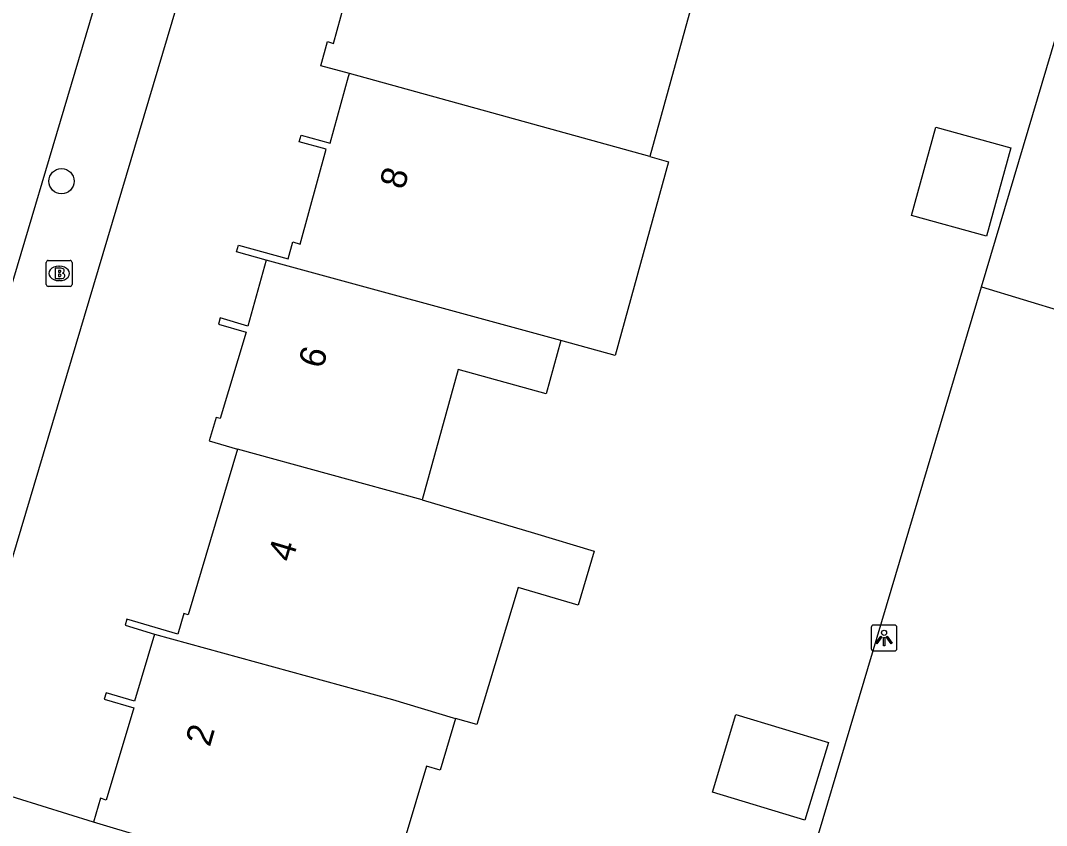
# Model space of a CAD drawing. Extents: x 162186 to 163152, y 385513 to 386513.
# Drawn here: x 162732.25 to 162771.96, y 386082.74 to 386113.9 of the extents above; entities that cross this region are included whole.
import ezdxf

# ---------------------------------------------------------------- set-up
doc = ezdxf.new("R2010")
doc.units = 0
for name, color, linetype in [('IMGEO_Boom', 7, 'Continuous'), ('IMGEO_Brandkraan', 7, 'Continuous'), ('IMGEO_Lichtpunt', 7, 'Continuous'), ('IMGEO_Pand', 7, 'Continuous'), ('IMGEO_Pand_nummerreeks', 7, 'Continuous'), ('IMGEO_Rijbaan_lokaal_open', 7, 'Continuous'), ('IMGEO_Voetpad_open', 7, 'Continuous')]:
    doc.layers.add(name, color=color, linetype=linetype)

msp = doc.modelspace()

# ---------------------------------------------------------------- linework, layer by layer
at = {"layer": 'IMGEO_Boom'}
msp.add_circle((162733.841, 386107.675), 0.489, dxfattribs=at)
at = {"layer": 'IMGEO_Brandkraan'}
for p, q in [((162733.249, 386103.681), (162733.249, 386104.533)), ((162733.324, 386104.607), (162734.176, 386104.607)), ((162733.737, 386104.387), (162733.762, 386104.387)), ((162734.25, 386104.533), (162734.25, 386103.681)), ((162734.176, 386103.607), (162733.324, 386103.607)), ((162733.76, 386103.827), (162733.735, 386103.827))]:
    msp.add_line(p, q, dxfattribs=at)
for points in [[(162733.249, 386103.681), (162733.249, 386104.533)], [(162733.324, 386104.607), (162734.176, 386104.607)], [(162733.597, 386104.307), (162733.597, 386103.907), (162733.81, 386103.907)], [(162733.828, 386104.307), (162733.597, 386104.307)], [(162734.25, 386104.533), (162734.25, 386103.681)], [(162733.776, 386104.226), (162733.722, 386104.226), (162733.722, 386104.15)], [(162733.722, 386104.15), (162733.775, 386104.15)], [(162733.784, 386104.074), (162733.722, 386104.074), (162733.722, 386103.993)], [(162733.722, 386103.993), (162733.784, 386103.993)], [(162734.176, 386103.607), (162733.324, 386103.607)]]:
    msp.add_lwpolyline(points, dxfattribs=at)
for centre, radius, start, end in [((162733.326, 386104.531), 0.0765, 91.552, 178.448), ((162733.326, 386104.531), 0.0765, 91.552, 178.448), ((162733.832, 386104.162), 0.145, 59.4692, 91.5367), ((162733.857, 386104.209), 0.0922, 285.5137, 58.1501), ((162734.174, 386104.531), 0.0765, 1.552, 88.448), ((162734.174, 386104.531), 0.0765, 1.552, 88.448), ((162733.777, 386104.188), 0.0379, 267.8285, 90.9355), ((162733.785, 386104.033), 0.0404, 269.8759, 90.5077), ((162733.816, 386104.158), 0.251, 268.6676, 293.5347), ((162733.862, 386104.017), 0.105, 301.3115, 78.989), ((162733.326, 386103.683), 0.0765, 181.552, 268.448), ((162733.326, 386103.683), 0.0765, 181.552, 268.448), ((162734.174, 386103.683), 0.0765, 271.552, 358.448), ((162734.174, 386103.683), 0.0765, 271.552, 358.448)]:
    msp.add_arc(centre, radius, start, end, dxfattribs=at)
for centre, major_axis, ratio, start_param, end_param in [((162733.736, 386104.107), (-0.387, 0.002), 0.722429, 4.712389, 7.853982), ((162733.761, 386104.107), (-0.39, 0.002), 0.717154, 1.570796, 4.712389)]:
    msp.add_ellipse(centre, major_axis=major_axis, ratio=ratio, start_param=start_param, end_param=end_param, dxfattribs=at)
at = {"layer": 'IMGEO_Lichtpunt'}
for p, q in [((162765.173, 386090.4), (162765.173, 386089.593)), ((162765.173, 386090.4), (162765.173, 386089.593)), ((162766.075, 386090.495), (162765.267, 386090.495)), ((162766.075, 386090.495), (162765.267, 386090.495)), ((162766.169, 386089.593), (162766.169, 386090.4)), ((162766.169, 386089.593), (162766.169, 386090.4)), ((162765.267, 386089.499), (162766.075, 386089.499)), ((162765.267, 386089.499), (162766.075, 386089.499))]:
    msp.add_line(p, q, dxfattribs=at)
for points in [[(162765.547, 386090.064), (162765.586, 386090.036), (162765.398, 386089.774), (162765.36, 386089.801), (162765.547, 386090.064)], [(162765.649, 386090.016), (162765.696, 386090.016), (162765.696, 386089.694), (162765.649, 386089.694), (162765.649, 386090.016)], [(162765.759, 386090.036), (162765.797, 386090.063), (162765.984, 386089.801), (162765.945, 386089.773), (162765.759, 386090.036)]]:
    msp.add_lwpolyline(points, dxfattribs=at)
msp.add_circle((162765.672, 386090.198), 0.0994, dxfattribs=at)
for centre, start, end in [((162765.267, 386090.4), 90, 180), ((162765.267, 386090.4), 90, 180), ((162766.075, 386090.4), 0, 90), ((162766.075, 386090.4), 0, 90), ((162765.267, 386089.593), 180, 270), ((162765.267, 386089.593), 180, 270), ((162766.075, 386089.593), 270, 0), ((162766.075, 386089.593), 270, 360)]:
    msp.add_arc(centre, 0.0946, start, end, dxfattribs=at)
at = {"layer": 'IMGEO_Pand'}
for points in [[(162744.982, 386111.839), (162743.872, 386112.145), (162744.129, 386113.077), (162744.368, 386113.011), (162745.366, 386116.628), (162744.272, 386116.931), (162744.34, 386117.177), (162745.53, 386116.849), (162746.257, 386119.483)], [(162755.389, 386117.025), (162757.653, 386116.399), (162758.675, 386116.117), (162756.608, 386108.631)], [(162741.758, 386104.626), (162740.618, 386104.942), (162740.689, 386105.202), (162742.609, 386104.672), (162742.789, 386105.325), (162743.077, 386105.245), (162744.089, 386108.913), (162743.037, 386109.204), (162743.109, 386109.464), (162744.24, 386109.152), (162744.951, 386111.727), (162744.982, 386111.839)], [(162756.608, 386108.631), (162744.982, 386111.839)], [(162767.679, 386109.77), (162770.582, 386108.969), (162769.637, 386105.548), (162766.734, 386106.349), (162767.679, 386109.77)], [(162756.608, 386108.631), (162757.333, 386108.43), (162755.263, 386100.934), (162753.169, 386101.512)], [(162741.758, 386104.626), (162741.053, 386102.071), (162739.987, 386102.389), (162739.914, 386102.144), (162740.981, 386101.827), (162739.986, 386098.488), (162739.824, 386098.536), (162739.553, 386097.627), (162740.655, 386097.299)], [(162753.169, 386101.512), (162741.758, 386104.626)], [(162753.169, 386101.512), (162752.598, 386099.443), (162749.191, 386100.383), (162747.794, 386095.346)], [(162740.655, 386097.299), (162738.746, 386090.892), (162738.575, 386090.943), (162738.336, 386090.144), (162736.371, 386090.729), (162736.3, 386090.49), (162737.443, 386090.149)], [(162747.794, 386095.346), (162740.655, 386097.299)], [(162747.794, 386095.346), (162752.141, 386094.051), (162754.46, 386093.36), (162753.838, 386091.271), (162751.517, 386091.957), (162749.91, 386086.652), (162749.086, 386086.882)], [(162737.443, 386090.149), (162736.667, 386087.546), (162735.563, 386087.875), (162735.49, 386087.63), (162736.634, 386087.29), (162735.572, 386083.726), (162735.351, 386083.791), (162735.074, 386082.862)], [(162737.443, 386090.149), (162746.654, 386087.61), (162748.993, 386086.91), (162749.086, 386086.882)], [(162749.086, 386086.882), (162748.488, 386084.875), (162747.961, 386085.032), (162746.315, 386079.512)], [(162763.522, 386085.955), (162762.609, 386082.944), (162759.03, 386084.029), (162759.942, 386087.04), (162763.522, 386085.955)], [(162746.315, 386079.512), (162743.573, 386080.329), (162735.074, 386082.862)]]:
    msp.add_lwpolyline(points, dxfattribs=at)
at = {"layer": 'IMGEO_Rijbaan_lokaal_open'}
for points in [[(162735.486, 386115.734), (162730.41, 386098.664), (162727.044, 386087.256)], [(162746.315, 386079.512), (162758.579, 386075.961), (162758.794, 386075.903), (162759.013, 386075.865), (162759.235, 386075.846), (162759.457, 386075.847), (162759.679, 386075.868), (162759.898, 386075.909), (162760.112, 386075.969), (162760.32, 386076.049), (162760.52, 386076.146), (162760.711, 386076.261), (162760.89, 386076.392), (162761.057, 386076.539), (162761.211, 386076.7), (162761.349, 386076.875), (162761.471, 386077.061), (162761.576, 386077.257), (162761.663, 386077.462), (162761.733, 386077.677), (162769.446, 386103.583)], [(162769.446, 386103.583), (162772.668, 386102.613)], [(162735.074, 386082.862), (162731.096, 386084.112), (162730.945, 386084.185), (162730.791, 386084.277), (162730.647, 386084.381), (162730.512, 386084.498), (162730.389, 386084.627), (162730.277, 386084.766), (162730.178, 386084.915), (162730.093, 386085.072), (162730.023, 386085.236), (162729.967, 386085.406), (162729.927, 386085.579), (162729.902, 386085.756), (162729.893, 386085.934), (162729.9, 386086.113), (162729.923, 386086.29), (162729.962, 386086.464)]]:
    msp.add_lwpolyline(points, dxfattribs=at)
at = {"layer": 'IMGEO_Voetpad_open'}
for points in [[(162729.962, 386086.464), (162748.726, 386149.462), (162748.746, 386149.525)], [(162769.446, 386103.583), (162780.141, 386139.505), (162780.193, 386139.71)]]:
    msp.add_lwpolyline(points, dxfattribs=at)

# ---------------------------------------------------------------- texts
at = {"layer": 'IMGEO_Pand_nummerreeks'}
for s, rotation, p in [('8', 73.8772, (162747.09, 386107.315)), ('6', 73.8994, (162743.946, 386100.383)), ('4', 73.4074, (162742.766, 386092.895)), ('2', 73.7593, (162739.579, 386085.753))]:
    msp.add_text(s, height=1, rotation=rotation, dxfattribs=at).set_placement(p)

doc.saveas('drawing.dxf')
